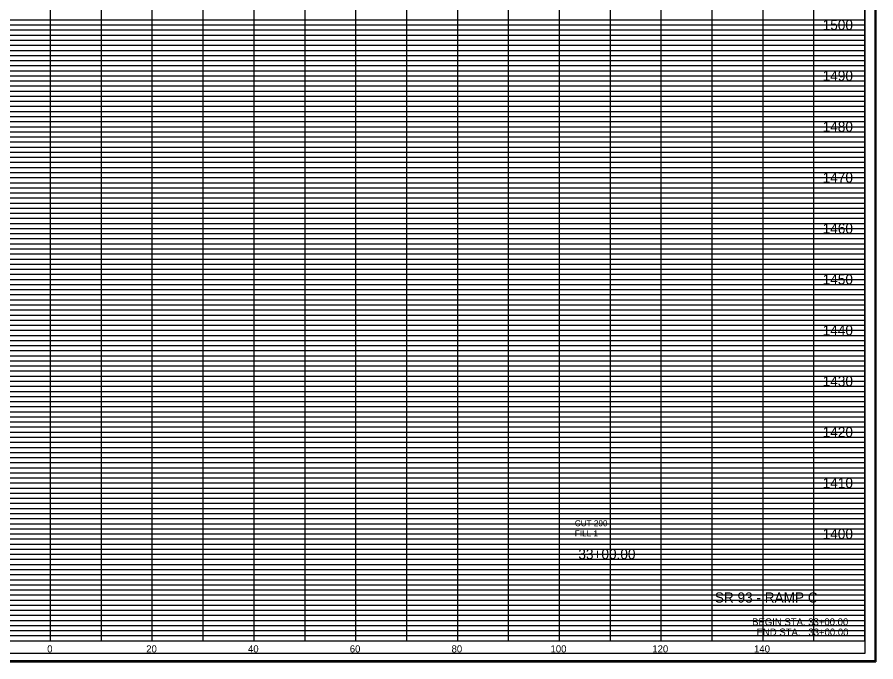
# Model space of a CAD drawing. Extents: x 980 to 2064, y 978 to 2267.
# Drawn here: x 1523.4 to 1692.2, y 1255.9 to 1382.5 of the extents above; entities that cross this region are included whole.
import ezdxf

# ---------------------------------------------------------------- set-up
doc = ezdxf.new("R2010")
doc.units = 0
for name, color, linetype in [('Default', 7, 'Continuous'), ('DESIGN - SHEET - Corner Text', 7, 'Continuous'), ('DESIGN - SHEET - Light Grid', 7, 'Continuous'), ('DESIGN - SHEET - Linework', 7, 'Continuous'), ('DESIGN - SHEET - Plot Shape', 7, 'Continuous'), ('DESIGN - TYPICAL - Text', 7, 'Continuous')]:
    doc.layers.add(name, color=color, linetype=linetype)

msp = doc.modelspace()

# ---------------------------------------------------------------- linework, layer by layer
at = {"layer": 'DESIGN - SHEET - Light Grid'}
for p, q in [((1450, 1382), (1530, 1382)), ((1530, 1382), (1610, 1382)), ((1610, 1382), (1690, 1382)), ((1450, 1381), (1530, 1381)), ((1530, 1381), (1610, 1381)), ((1610, 1381), (1690, 1381)), ((1450, 1379), (1530, 1379)), ((1530, 1379), (1610, 1379)), ((1610, 1379), (1690, 1379)), ((1450, 1378), (1530, 1378)), ((1450, 1377), (1530, 1377)), ((1530, 1378), (1610, 1378)), ((1530, 1377), (1610, 1377)), ((1610, 1378), (1690, 1378)), ((1610, 1377), (1690, 1377)), ((1450, 1376), (1530, 1376)), ((1530, 1376), (1610, 1376)), ((1610, 1376), (1690, 1376)), ((1450, 1375), (1530, 1375)), ((1450, 1374), (1530, 1374)), ((1530, 1375), (1610, 1375)), ((1530, 1374), (1610, 1374)), ((1610, 1375), (1690, 1375)), ((1610, 1374), (1690, 1374)), ((1450, 1373), (1530, 1373)), ((1450, 1372), (1530, 1372)), ((1530, 1373), (1610, 1373)), ((1530, 1372), (1610, 1372)), ((1610, 1373), (1690, 1373)), ((1610, 1372), (1690, 1372)), ((1450, 1371), (1530, 1371)), ((1530, 1371), (1610, 1371)), ((1610, 1371), (1690, 1371)), ((1450, 1369), (1530, 1369)), ((1530, 1369), (1610, 1369)), ((1610, 1369), (1690, 1369)), ((1450, 1368), (1530, 1368)), ((1450, 1367), (1530, 1367)), ((1530, 1368), (1610, 1368)), ((1530, 1367), (1610, 1367)), ((1610, 1368), (1690, 1368)), ((1610, 1367), (1690, 1367)), ((1450, 1366), (1530, 1366)), ((1530, 1366), (1610, 1366)), ((1610, 1366), (1690, 1366)), ((1450, 1365), (1530, 1365)), ((1450, 1364), (1530, 1364)), ((1530, 1365), (1610, 1365)), ((1530, 1364), (1610, 1364)), ((1610, 1365), (1690, 1365)), ((1610, 1364), (1690, 1364)), ((1450, 1363), (1530, 1363)), ((1450, 1362), (1530, 1362)), ((1530, 1363), (1610, 1363)), ((1530, 1362), (1610, 1362)), ((1610, 1363), (1690, 1363)), ((1610, 1362), (1690, 1362)), ((1450, 1361), (1530, 1361)), ((1530, 1361), (1610, 1361)), ((1610, 1361), (1690, 1361)), ((1450, 1359), (1530, 1359)), ((1530, 1359), (1610, 1359)), ((1610, 1359), (1690, 1359)), ((1450, 1358), (1530, 1358)), ((1450, 1357), (1530, 1357)), ((1530, 1358), (1610, 1358)), ((1530, 1357), (1610, 1357)), ((1610, 1358), (1690, 1358)), ((1610, 1357), (1690, 1357)), ((1450, 1356), (1530, 1356)), ((1450, 1355), (1530, 1355)), ((1530, 1356), (1610, 1356)), ((1530, 1355), (1610, 1355)), ((1610, 1356), (1690, 1356)), ((1610, 1355), (1690, 1355)), ((1450, 1354), (1530, 1354)), ((1530, 1354), (1610, 1354)), ((1610, 1354), (1690, 1354)), ((1450, 1353), (1530, 1353)), ((1450, 1352), (1530, 1352)), ((1530, 1353), (1610, 1353)), ((1530, 1352), (1610, 1352)), ((1610, 1353), (1690, 1353)), ((1610, 1352), (1690, 1352)), ((1450, 1351), (1530, 1351)), ((1530, 1351), (1610, 1351)), ((1610, 1351), (1690, 1351)), ((1450, 1349), (1530, 1349)), ((1530, 1349), (1610, 1349)), ((1610, 1349), (1690, 1349)), ((1450, 1348), (1530, 1348)), ((1450, 1347), (1530, 1347)), ((1530, 1348), (1610, 1348)), ((1530, 1347), (1610, 1347)), ((1610, 1348), (1690, 1348)), ((1610, 1347), (1690, 1347)), ((1450, 1346), (1530, 1346)), ((1450, 1345), (1530, 1345)), ((1530, 1346), (1610, 1346)), ((1530, 1345), (1610, 1345)), ((1610, 1346), (1690, 1346)), ((1610, 1345), (1690, 1345)), ((1450, 1344), (1530, 1344)), ((1530, 1344), (1610, 1344)), ((1610, 1344), (1690, 1344)), ((1450, 1343), (1530, 1343)), ((1450, 1342), (1530, 1342)), ((1530, 1343), (1610, 1343)), ((1530, 1342), (1610, 1342)), ((1610, 1343), (1690, 1343)), ((1610, 1342), (1690, 1342)), ((1450, 1341), (1530, 1341)), ((1530, 1341), (1610, 1341)), ((1610, 1341), (1690, 1341)), ((1450, 1339), (1530, 1339)), ((1530, 1339), (1610, 1339)), ((1610, 1339), (1690, 1339)), ((1450, 1338), (1530, 1338)), ((1450, 1337), (1530, 1337)), ((1530, 1338), (1610, 1338)), ((1530, 1337), (1610, 1337)), ((1610, 1338), (1690, 1338)), ((1610, 1337), (1690, 1337)), ((1450, 1336), (1530, 1336)), ((1450, 1335), (1530, 1335)), ((1530, 1336), (1610, 1336)), ((1530, 1335), (1610, 1335)), ((1610, 1336), (1690, 1336)), ((1610, 1335), (1690, 1335)), ((1450, 1334), (1530, 1334)), ((1450, 1333), (1530, 1333)), ((1530, 1334), (1610, 1334)), ((1530, 1333), (1610, 1333)), ((1610, 1334), (1690, 1334)), ((1610, 1333), (1690, 1333)), ((1450, 1332), (1530, 1332)), ((1530, 1332), (1610, 1332)), ((1610, 1332), (1690, 1332)), ((1450, 1331), (1530, 1331)), ((1530, 1331), (1610, 1331)), ((1610, 1331), (1690, 1331)), ((1450, 1329), (1530, 1329)), ((1450, 1328), (1530, 1328)), ((1530, 1329), (1610, 1329)), ((1530, 1328), (1610, 1328)), ((1610, 1329), (1690, 1329)), ((1610, 1328), (1690, 1328)), ((1450, 1327), (1530, 1327)), ((1530, 1327), (1610, 1327)), ((1610, 1327), (1690, 1327)), ((1450, 1326), (1530, 1326)), ((1450, 1325), (1530, 1325)), ((1530, 1326), (1610, 1326)), ((1530, 1325), (1610, 1325)), ((1610, 1326), (1690, 1326)), ((1610, 1325), (1690, 1325)), ((1450, 1324), (1530, 1324)), ((1450, 1323), (1530, 1323)), ((1530, 1324), (1610, 1324)), ((1530, 1323), (1610, 1323)), ((1610, 1324), (1690, 1324)), ((1610, 1323), (1690, 1323)), ((1450, 1322), (1530, 1322)), ((1530, 1322), (1610, 1322)), ((1610, 1322), (1690, 1322)), ((1450, 1321), (1530, 1321)), ((1530, 1321), (1610, 1321)), ((1610, 1321), (1690, 1321)), ((1450, 1319), (1530, 1319)), ((1450, 1318), (1530, 1318)), ((1530, 1319), (1610, 1319)), ((1530, 1318), (1610, 1318)), ((1610, 1319), (1690, 1319)), ((1610, 1318), (1690, 1318)), ((1450, 1317), (1530, 1317)), ((1530, 1317), (1610, 1317)), ((1610, 1317), (1690, 1317)), ((1450, 1316), (1530, 1316)), ((1450, 1315), (1530, 1315)), ((1530, 1316), (1610, 1316)), ((1530, 1315), (1610, 1315)), ((1610, 1316), (1690, 1316)), ((1610, 1315), (1690, 1315)), ((1450, 1314), (1530, 1314)), ((1450, 1313), (1530, 1313)), ((1530, 1314), (1610, 1314)), ((1530, 1313), (1610, 1313)), ((1610, 1314), (1690, 1314)), ((1610, 1313), (1690, 1313)), ((1450, 1312), (1530, 1312)), ((1530, 1312), (1610, 1312)), ((1610, 1312), (1690, 1312)), ((1450, 1311), (1530, 1311)), ((1530, 1311), (1610, 1311)), ((1610, 1311), (1690, 1311)), ((1450, 1309), (1530, 1309)), ((1450, 1308), (1530, 1308)), ((1530, 1309), (1610, 1309)), ((1530, 1308), (1610, 1308)), ((1610, 1309), (1690, 1309)), ((1610, 1308), (1690, 1308)), ((1450, 1307), (1530, 1307)), ((1450, 1306), (1530, 1306)), ((1530, 1307), (1610, 1307)), ((1530, 1306), (1610, 1306)), ((1610, 1307), (1690, 1307)), ((1610, 1306), (1690, 1306)), ((1450, 1305), (1530, 1305)), ((1530, 1305), (1610, 1305)), ((1610, 1305), (1690, 1305)), ((1450, 1304), (1530, 1304)), ((1450, 1303), (1530, 1303)), ((1530, 1304), (1610, 1304)), ((1530, 1303), (1610, 1303)), ((1610, 1304), (1690, 1304)), ((1610, 1303), (1690, 1303)), ((1450, 1302), (1530, 1302)), ((1450, 1301), (1530, 1301)), ((1530, 1302), (1610, 1302)), ((1530, 1301), (1610, 1301)), ((1610, 1302), (1690, 1302)), ((1610, 1301), (1690, 1301)), ((1450, 1299), (1530, 1299)), ((1450, 1298), (1530, 1298)), ((1530, 1299), (1610, 1299)), ((1530, 1298), (1610, 1298)), ((1610, 1299), (1690, 1299)), ((1610, 1298), (1690, 1298)), ((1450, 1297), (1530, 1297)), ((1450, 1296), (1530, 1296)), ((1530, 1297), (1610, 1297)), ((1530, 1296), (1610, 1296)), ((1610, 1297), (1690, 1297)), ((1610, 1296), (1690, 1296)), ((1450, 1295), (1530, 1295)), ((1530, 1295), (1610, 1295)), ((1610, 1295), (1690, 1295)), ((1450, 1294), (1530, 1294)), ((1450, 1293), (1530, 1293)), ((1530, 1294), (1610, 1294)), ((1530, 1293), (1610, 1293)), ((1610, 1294), (1690, 1294)), ((1610, 1293), (1690, 1293)), ((1450, 1292), (1530, 1292)), ((1450, 1291), (1530, 1291)), ((1530, 1292), (1610, 1292)), ((1530, 1291), (1610, 1291)), ((1610, 1292), (1690, 1292)), ((1610, 1291), (1690, 1291)), ((1450, 1289), (1530, 1289)), ((1450, 1288), (1530, 1288)), ((1530, 1289), (1610, 1289)), ((1530, 1288), (1610, 1288)), ((1610, 1289), (1690, 1289)), ((1610, 1288), (1690, 1288)), ((1450, 1287), (1530, 1287)), ((1450, 1286), (1530, 1286)), ((1530, 1287), (1610, 1287)), ((1530, 1286), (1610, 1286)), ((1610, 1287), (1690, 1287)), ((1610, 1286), (1690, 1286)), ((1450, 1285), (1530, 1285)), ((1530, 1285), (1610, 1285)), ((1610, 1285), (1690, 1285)), ((1450, 1284), (1530, 1284)), ((1450, 1283), (1530, 1283)), ((1530, 1284), (1610, 1284)), ((1530, 1283), (1610, 1283)), ((1610, 1284), (1690, 1284)), ((1610, 1283), (1690, 1283)), ((1450, 1282), (1530, 1282)), ((1450, 1281), (1530, 1281)), ((1530, 1282), (1610, 1282)), ((1530, 1281), (1610, 1281)), ((1610, 1282), (1690, 1282)), ((1610, 1281), (1690, 1281)), ((1450, 1279), (1530, 1279)), ((1530, 1279), (1610, 1279)), ((1610, 1279), (1690, 1279)), ((1450, 1278), (1530, 1278)), ((1530, 1278), (1610, 1278)), ((1610, 1278), (1690, 1278)), ((1450, 1277), (1530, 1277)), ((1450, 1276), (1530, 1276)), ((1530, 1277), (1610, 1277)), ((1530, 1276), (1610, 1276)), ((1610, 1277), (1690, 1277)), ((1610, 1276), (1690, 1276)), ((1450, 1275), (1530, 1275)), ((1450, 1274), (1530, 1274)), ((1530, 1275), (1610, 1275)), ((1530, 1274), (1610, 1274)), ((1610, 1275), (1690, 1275)), ((1610, 1274), (1690, 1274)), ((1450, 1273), (1530, 1273)), ((1530, 1273), (1610, 1273)), ((1610, 1273), (1690, 1273)), ((1450, 1272), (1530, 1272)), ((1450, 1271), (1530, 1271)), ((1530, 1272), (1610, 1272)), ((1530, 1271), (1610, 1271)), ((1610, 1272), (1690, 1272)), ((1610, 1271), (1690, 1271)), ((1450, 1269), (1530, 1269)), ((1530, 1269), (1610, 1269)), ((1610, 1269), (1690, 1269)), ((1450, 1268), (1530, 1268)), ((1530, 1268), (1610, 1268)), ((1610, 1268), (1690, 1268)), ((1450, 1267), (1530, 1267)), ((1450, 1266), (1530, 1266)), ((1530, 1267), (1610, 1267)), ((1530, 1266), (1610, 1266)), ((1610, 1267), (1690, 1267)), ((1610, 1266), (1690, 1266)), ((1450, 1265), (1530, 1265)), ((1450, 1264), (1530, 1264)), ((1530, 1265), (1610, 1265)), ((1530, 1264), (1610, 1264)), ((1610, 1265), (1690, 1265)), ((1610, 1264), (1690, 1264)), ((1450, 1263), (1530, 1263)), ((1530, 1263), (1610, 1263)), ((1610, 1263), (1690, 1263)), ((1450, 1262), (1530, 1262)), ((1450, 1261), (1530, 1261)), ((1530, 1262), (1610, 1262)), ((1530, 1261), (1610, 1261)), ((1610, 1262), (1690, 1262)), ((1610, 1261), (1690, 1261))]:
    msp.add_line(p, q, dxfattribs=at)
at = {"layer": 'DESIGN - SHEET - Linework'}
for p, q in [((1692.17, 1474.14), (1692.17, 1255.86)), ((1530, 1260), (1530, 1470)), ((1540, 1260), (1540, 1470)), ((1550, 1260), (1550, 1470)), ((1560, 1260), (1560, 1470)), ((1570, 1260), (1570, 1470)), ((1580, 1260), (1580, 1470)), ((1590, 1260), (1590, 1470)), ((1600, 1260), (1600, 1470)), ((1610, 1260), (1610, 1470)), ((1620, 1260), (1620, 1470)), ((1630, 1260), (1630, 1470)), ((1640, 1260), (1640, 1470)), ((1650, 1260), (1650, 1460)), ((1660, 1260), (1660, 1460)), ((1670, 1260), (1670, 1460)), ((1680, 1260), (1680, 1460)), ((1370, 1380), (1690, 1380)), ((1370, 1370), (1690, 1370)), ((1370, 1360), (1690, 1360)), ((1370, 1350), (1690, 1350)), ((1370, 1340), (1690, 1340)), ((1370, 1330), (1690, 1330)), ((1370, 1320), (1690, 1320)), ((1370, 1310), (1690, 1310)), ((1370, 1300), (1690, 1300)), ((1370, 1290), (1690, 1290)), ((1370, 1280), (1690, 1280)), ((1370, 1270), (1690, 1270)), ((1351.77, 1255.86), (1692.17, 1255.86))]:
    msp.add_line(p, q, dxfattribs=at)
msp.add_lwpolyline([(1370, 1470), (1370, 1260), (1690, 1260), (1690, 1470), (1370, 1470)], dxfattribs=at)
at = {"layer": 'DESIGN - SHEET - Plot Shape'}
for points in [[(1351.97, 1473.94), (1691.97, 1473.94), (1691.97, 1256.06), (1351.97, 1256.06)], [(1361.5, 1470), (1690, 1470), (1690, 1257.5), (1361.5, 1257.5)]]:
    msp.add_lwpolyline(points, close=True, dxfattribs=at)

# ---------------------------------------------------------------- texts
at = {"layer": 'Default'}
for s, height, p in [('     1500     ', 2, (1678.01, 1380)), ('     1490     ', 2, (1678.01, 1370)), ('     1480     ', 2, (1678.01, 1360)), ('     1470     ', 2, (1678.01, 1350)), ('     1460     ', 2, (1678.01, 1340)), ('     1450     ', 2, (1678.01, 1330)), ('     1440     ', 2, (1678.01, 1320)), ('     1430     ', 2, (1678.01, 1310)), ('     1420     ', 2, (1678.01, 1300)), ('     1410     ', 2, (1678.01, 1290)), ('     1400     ', 2, (1678.01, 1280)), ('     33+00.00     ', 2, (1630, 1276.03)), ('     0     ', 1.4, (1526.74, 1257.7)), ('     0     ', 1.4, (1526.74, 1257.7)), ('     20     ', 1.4, (1546.2, 1257.7)), ('     40     ', 1.4, (1566.2, 1257.7)), ('     60     ', 1.4, (1586.2, 1257.7)), ('     80     ', 1.4, (1606.2, 1257.7)), ('     100     ', 1.4, (1625.65, 1257.7)), ('     120     ', 1.4, (1645.65, 1257.7)), ('     140     ', 1.4, (1665.65, 1257.7))]:
    msp.add_text(s, height=height, dxfattribs=at).set_placement(p)
at = {"layer": 'DESIGN - SHEET - Corner Text'}
for s, height, p in [('SR 93 - RAMP C', 2, (1660.53, 1267.5)), ('BEGIN STA. 33+00.00', 1.4, (1667.86, 1263)), ('END STA.   33+00.00', 1.4, (1668.73, 1261))]:
    msp.add_text(s, height=height, dxfattribs=at).set_placement(p)
at = {"layer": 'DESIGN - TYPICAL - Text'}
for s, p in [('CUT 290', (1633.02, 1282.49)), ('FILL 1', (1633.02, 1280.49))]:
    msp.add_text(s, height=1.2, dxfattribs=at).set_placement(p)

doc.saveas('drawing.dxf')
